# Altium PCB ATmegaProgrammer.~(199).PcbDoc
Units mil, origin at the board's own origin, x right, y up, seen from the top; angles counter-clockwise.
Board outline 2130 x 2720 mil, 2 copper layers (Top Layer, Bottom Layer); 13 components, 10 nets, 72 pads, 0 vias.
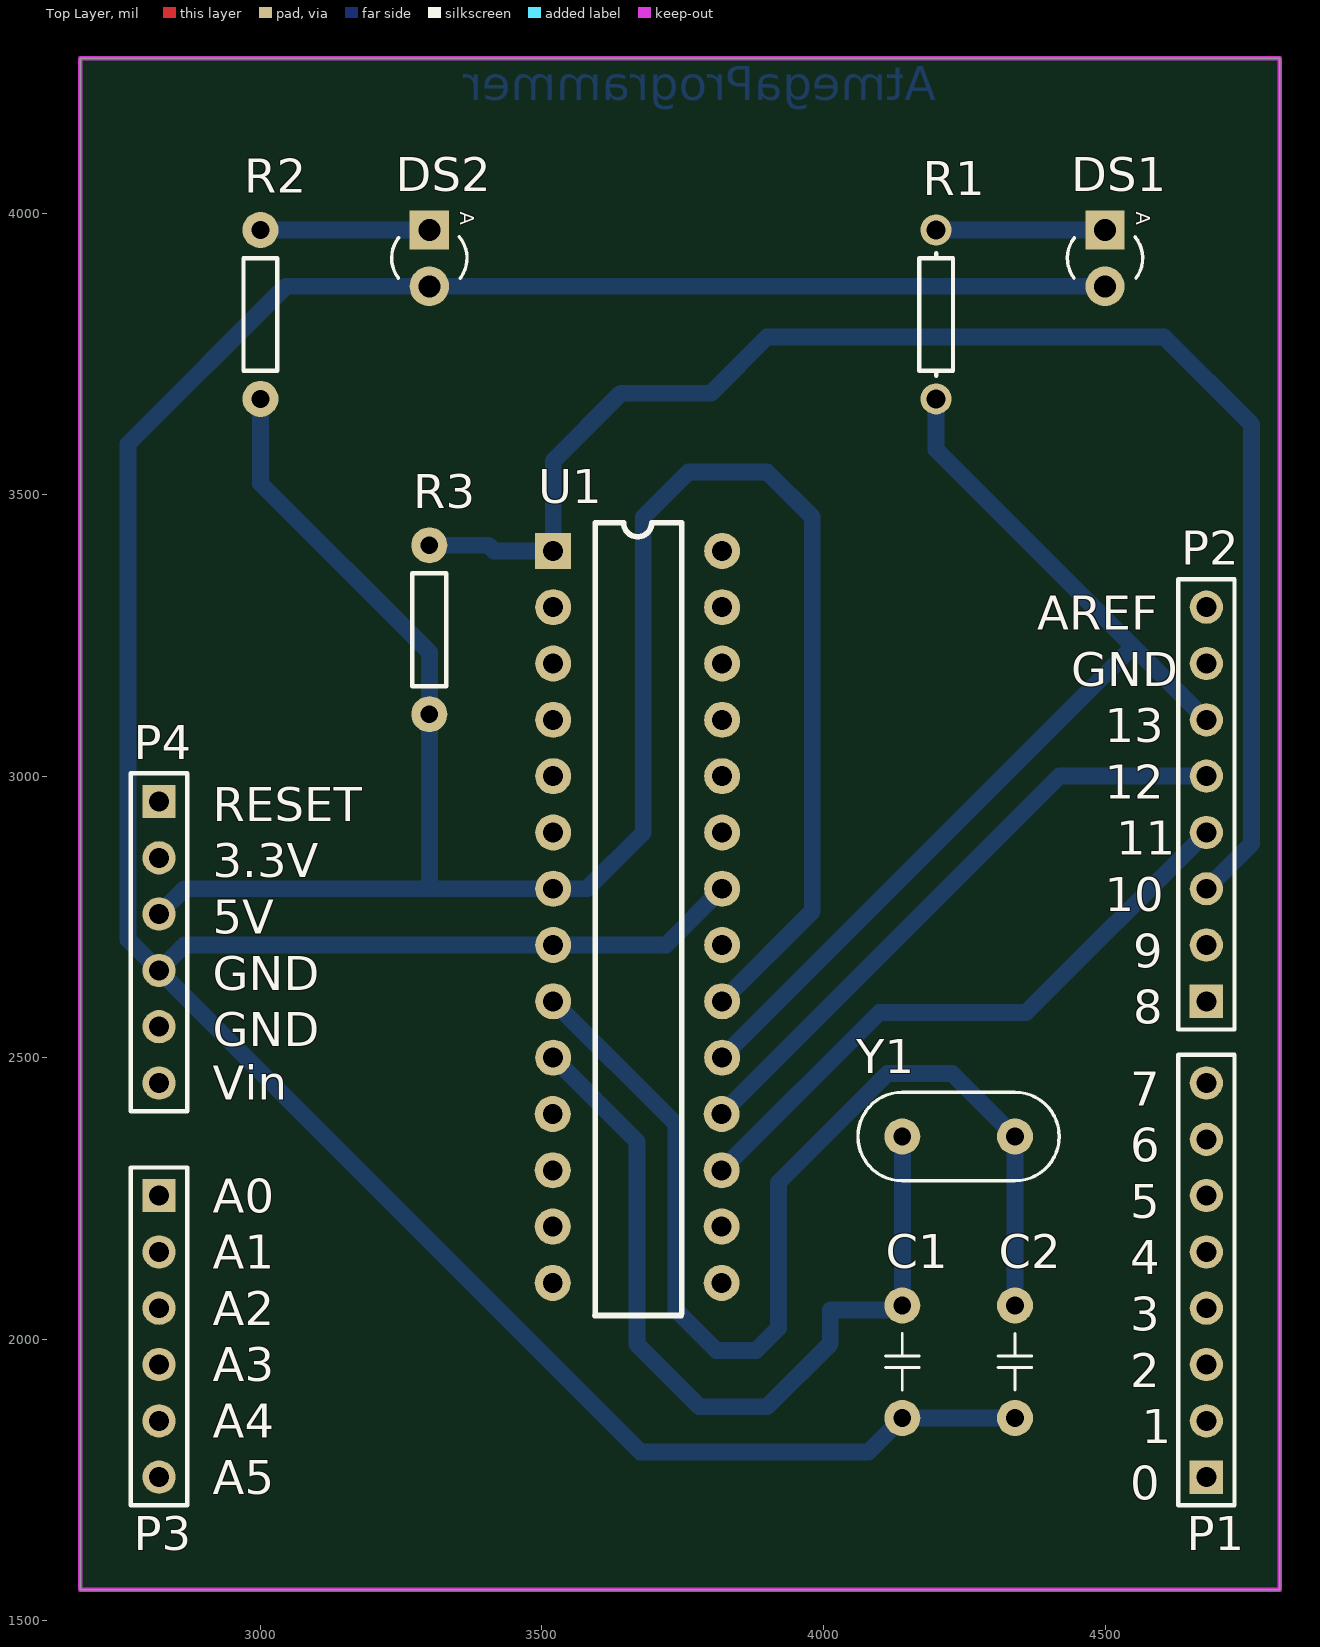
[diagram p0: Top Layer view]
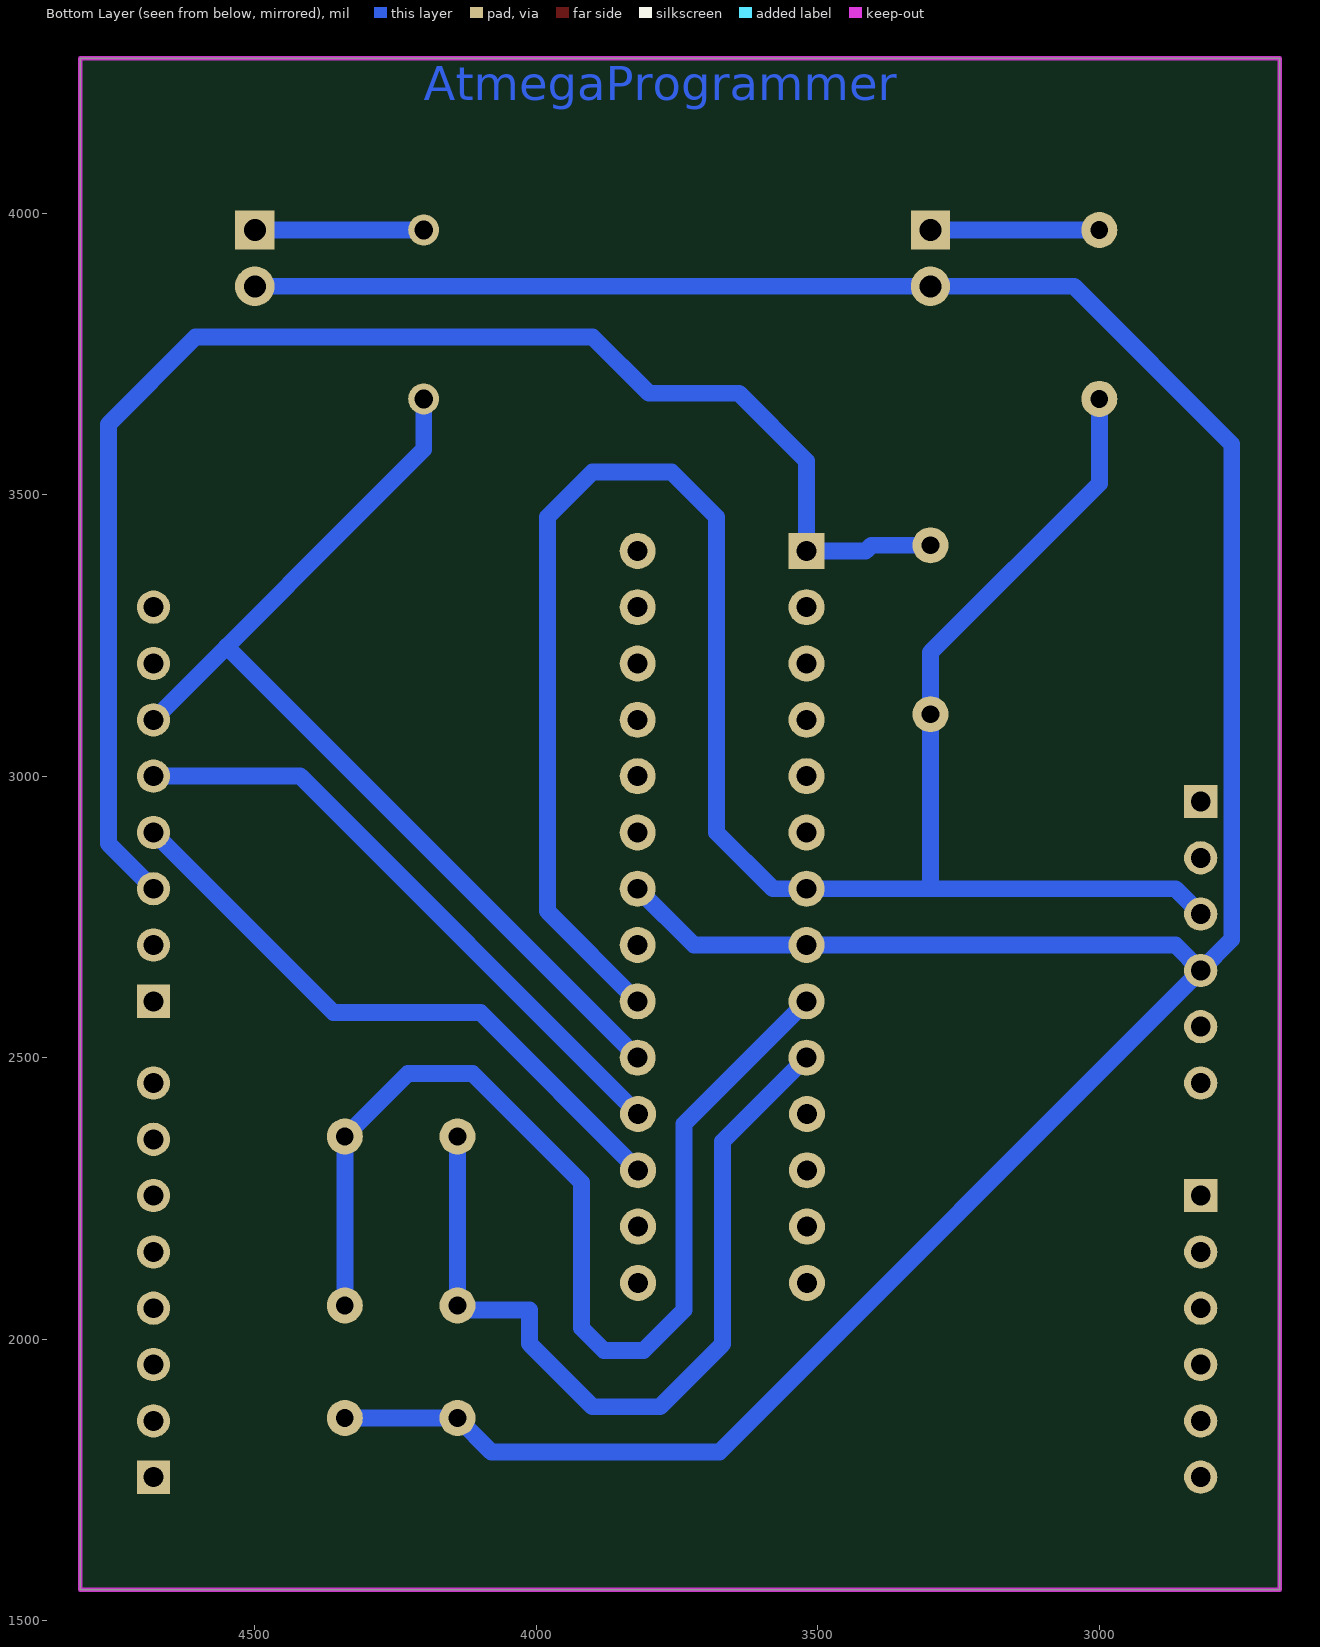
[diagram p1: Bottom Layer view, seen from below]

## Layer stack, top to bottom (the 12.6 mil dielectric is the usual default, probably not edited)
Top Layer: signal copper 1.4
Dielectric: dielectric 12.6, FR-4, Dk 4.8
Bottom Layer: signal copper 1.4

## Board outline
2680,1555 4810,1555 4810,4275 2680,4275

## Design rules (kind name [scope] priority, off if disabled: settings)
Clearance [All] p1: gap=10
PolygonConnect [All] p1: connectstyle=Relief reliefconductorwidth=10 reliefentries=4 polygonreliefangle="90 Angle"
RoutingLayers [All] p1: top layer_v5=FALSE bottom layer_v5=TRUE
RoutingVias [All] p1: holewidth=28 width=50 viastyle="Through Hole" minholewidth=28 minwidth=50 maxholewidth=28 maxwidth=50
SilkscreenOverComponentPads [All] p1: minsilkscreentomaskgap=10
SolderMaskExpansion [All] p1: expansion=4
Width VCC [All] p1: maxlimit=40 minlimit=20 preferedwidth=30
Width GND [InNet('GND')] p2: maxlimit=40 minlimit=20 preferedwidth=30
Width [All] p3: maxlimit=30 minlimit=10 preferedwidth=20
26 further rules are at their usual default settings.

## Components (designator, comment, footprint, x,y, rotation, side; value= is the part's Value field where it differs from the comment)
C1 "20pF" C200 4140,1960 r180 top
C2 "20pF" C200 4340,1960 r180 top
DS1 "LED" LED-3mm_G 4500,3920 r270 top
DS2 "LED" LED-3mm_G 3300,3920 r270 top
P1 "Header 8" HDR1X8 4680,1755 r90 top
P2 "Header 8" HDR1X8 4680,2600 r90 top
P3 "Header 6" HDR1X6 2820,2255 r270 top
P4 "Header 6" HDR1X6 2820,2955 r270 top
R1 "Res1" AXIAL-0.3#1 4200,3820 r270 top
R2 "220" AXIAL-0.3#2 3000,3820 r270 top
R3 "10k" AXIAL-0.3#2 3300,3260 r270 top
U1 "ATmega328" DIP-28 3520,3400 r270 top
Y1 "16MHz" XTAL4-8 4240,2360 r180 top

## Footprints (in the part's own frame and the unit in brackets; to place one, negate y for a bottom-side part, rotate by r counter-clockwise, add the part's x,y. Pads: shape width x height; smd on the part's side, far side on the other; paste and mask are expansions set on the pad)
AXIAL-0.3#1 [mm] "Axial Device, Thru-Hole; 2 Leads; 0.3 in Pin Spacing"
  round 1.4 hole 0.85: 1(-3.81,0) 2(3.81,0)
  silkscreen extent -2.77,-0.76 2.77,0.76
AXIAL-0.3#2 [mm] "0.3\" Resistor; 2 Leads"
  round 1.626 hole 0.8: 1(-3.81,0) 2(3.81,0)
  silkscreen extent -2.54,-0.76 2.54,0.76, body extent -4.1,-1 4.19,1, height 2.19
C200 [mil] "鹅溅筿甧竟"
  round 64 hole 31.5: 1(0,100) 2(0,-100)
  silkscreen extent -30,-50 30,50, body extent -41,-136 39,135, height 354
DIP-28 [mil]
  rect 64x64 hole 35.43: 1(0,0)
  round 64 hole 35.43: 2(100,0) 3(200,0) 4(300,0) 5(400,0) 6(500,0) 7(600,0) 8(700,0) 9(800,0) 10(900,0) 11(1000,-0.79) 12(1100,-0.79) 13(1200,-0.79) 14(1300,-0.79) 15(1300,299.21) 16(1200,299.21) 17(1100,299.21) 18(1000,299.21) 19(900,300) 20(800,300) 21(700,300) 22(600,300) 23(500,300) 24(400,300) 25(300,300) 26(200,300) 27(100,300) 28(0,300)
  silkscreen extent -50,74 1358,228, body extent -53,-5 1358,304, height 209
HDR1X6 [mm] "Connector; Header; 6 Position"
  rect 1.5x1.5 hole 0.9: 1(0,0)
  round 1.5 hole 0.9: 2(2.54,0) 3(5.08,0) 4(7.62,0) 5(10.16,0) 6(12.7,0)
  silkscreen extent -1.27,-1.27 13.97,1.27
HDR1X8 [mm] "Connector; Header; 8 Position"
  rect 1.5x1.5 hole 0.9: 1(0,0)
  round 1.5 hole 0.9: 2(2.54,0) 3(5.08,0) 4(7.62,0) 5(10.16,0) 6(12.7,0) 7(15.24,0) 8(17.78,0)
  silkscreen extent -1.27,-1.27 19.05,1.27
LED-3mm_G [mil] "3mm LED_Green"
  rect 70x70 hole 39: 1(-50,0)
  round 70 hole 39: 2(50,0)
  silkscreen extent -38,-67 35,67, body extent -66,-68 67,66, height 181
XTAL4-8 [mil]
  round 64 hole 31.5: 1(-100,0) 2(100,0)
  silkscreen extent -179,-79 179,79, body extent -178,-80 192,79, height 157

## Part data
C1 C2: library part Cap, "Capacitor"
DS1 DS2: "Typical INFRARED GaAs LED"
P1 P2: "Header, 8-Pin"
P3 P4: "Header, 6-Pin"
R1: "Resistor"
R2 R3: library part Res, "Resistor"
U1: "Arduino"
Y1: library part XTAL, "Crystal Oscillator"

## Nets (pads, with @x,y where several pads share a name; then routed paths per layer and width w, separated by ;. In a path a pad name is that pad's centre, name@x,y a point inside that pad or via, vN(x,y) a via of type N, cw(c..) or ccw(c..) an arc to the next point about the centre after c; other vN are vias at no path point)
GND: C1.1 C2.1 DS1.2 DS2.2 P4.4 U1.8 U1.22 | length 5767.8
  Bottom Layer w30: U1.22 3720,2700 U1.8 2865,2700 P4.4 ; C2.1 C1.1 4080,1800 3675,1800 P4.4 ; DS1.2 DS2.2 3045,3870 2765,3590 2765,2710 P4.4
MISO: P2.5 U1.18 | length 1109.3
  Bottom Layer w30: U1.18 4419.21,3000 P2.5
MOSI: P2.4 U1.17 | length 1109.3
  Bottom Layer w30: U1.17 4099.21,2580 4360,2580 P2.4
NetC1_2: C1.2 U1.10 Y1.2 | length 1486.1
  Bottom Layer w30: U1.10 3669,2351 3669,1991 3780,1880 3900,1880 4012,1992 4012,2052 C1.2@4132,2052 ; C1.2 Y1.2
NetC2_2: C2.2 U1.9 Y1.1 | length 1971.8
  Bottom Layer w30: U1.9 3738,2382 3738,2051.69 3809.69,1980 3880,1980 3920,2020 3920,2278.35 4113.65,2472 4228,2472 Y1.1 C2.2
NetDS1_1: DS1.1 R1.1 | length 300
  Bottom Layer w30: R1.1 DS1.1
NetDS2_1: DS2.1 R2.1 | length 300
  Bottom Layer w30: R2.1 DS2.1
RESET: P2.3 R3.1 U1.1 | length 2637.6
  Bottom Layer w30: R3.1 3405,3410 3415,3400 U1.1 3520,3560 3640,3680 3800,3680 3900,3780 4605,3780 4760,3625 4760,2880 P2.3
SCK: P2.6 R1.2 U1.19 | length 1801.1
  Bottom Layer w30: U1.19 4549.95,3229.95 ; R1.2 4200,3580 P2.6
VCC: P4.3 R2.2 R3.2 U1.7 U1.20 | length 3766.9
  Bottom Layer w30: P4.3 2865,2800 3300,2800 ; R2.2 3000,3520 3300,3220 3300,2800 ; U1.20 3980,2760 3980,3460 3900,3540 3760,3540 3680,3460 3680,2900 3580,2800 3300,2800
pads on no net: P1.1 P1.2 P1.3 P1.4 P1.5 P1.6 P1.7 P1.8 P2.1 P2.2 P2.7 P2.8 P3.1 P3.2 P3.3 P3.4 P3.5 P3.6 P4.1 P4.2 P4.5 P4.6 U1.2 U1.3 U1.4 U1.5 U1.6 U1.11 U1.12 U1.13 U1.14 U1.15 U1.16 U1.21 U1.23 U1.24 U1.25 U1.26 U1.27 U1.28

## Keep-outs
Keep-Out Layer:
  the board outline again, w7.87

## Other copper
Bottom Layer:
  text "AtmegaProgrammer" at 4200,4200 h60

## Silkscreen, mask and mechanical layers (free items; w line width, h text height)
Top Overlay:
  lines w7.87: 0,0 0,200 ; 20,0 35,0 ; 55,0 195,0 ; 2770,2246.75 2770,2255
  text "AREF" at 4380.02,3260 h60
  text "GND" at 4440,3160 h60
  text "13" at 4499.96,3060 h60
  text "12" at 4499.96,2960 h60
  text "RESET" at 2915.05,2920 h60
  text "11" at 4519.95,2860 h60
  text "3.3V" at 2915.05,2820 h60
  text "10" at 4499.96,2760 h60
  text "5V" at 2915.05,2720 h60
  text "9" at 4549.94,2660 h60
  text "GND" at 2915.05,2620 h60
  text "8" at 4549.94,2560 h60
  text "GND" at 2915.05,2520 h60
  text "Vin" at 2915.05,2425 h60
  text "7" at 4544.94,2415 h60
  text "6" at 4544.94,2315 h60
  text "A0" at 2915.05,2225 h60
  text "5" at 4544.94,2215 h60
  text "A1" at 2915.05,2125 h60
  text "4" at 4544.94,2115 h60
  text "A2" at 2915.05,2025 h60
  text "3" at 4544.94,2015 h60
  text "A3" at 2915.05,1925 h60
  text "2" at 4544.94,1915 h60
  text "A4" at 2915.05,1825 h60
  text "1" at 4564.94,1815 h60
  text "A5" at 2915.05,1725 h60
  text "0" at 4544.94,1715 h60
